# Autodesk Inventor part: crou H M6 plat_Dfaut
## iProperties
Created: 2006-03
Part Number: crou H M6 plat_Dfaut
Document SubType Name: Modeling
Designer: Flavien MARTY
Author: Flavien MARTY
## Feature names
1. Base1
